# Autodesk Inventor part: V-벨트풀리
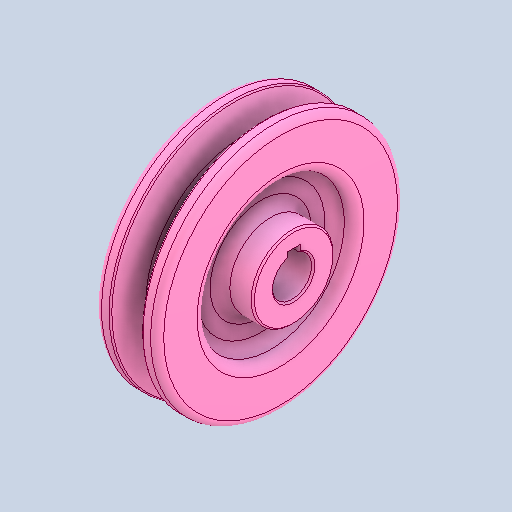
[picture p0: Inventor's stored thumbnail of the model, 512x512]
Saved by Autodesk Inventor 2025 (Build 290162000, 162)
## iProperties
Created: 2024-07
Part Number: V-벨트풀리
Material: 강철, 탄소
Document SubType Name: Modeling
Designer: SAMSUNG
Density: 7.87 g/cm^3
Appearance: 기본값
Author: jhkim
Sending System: Autodesk Inventor 2025
Preprocessor: ST-DEVELOPER v20
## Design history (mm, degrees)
feature "솔리드1"
node "솔리드2"
